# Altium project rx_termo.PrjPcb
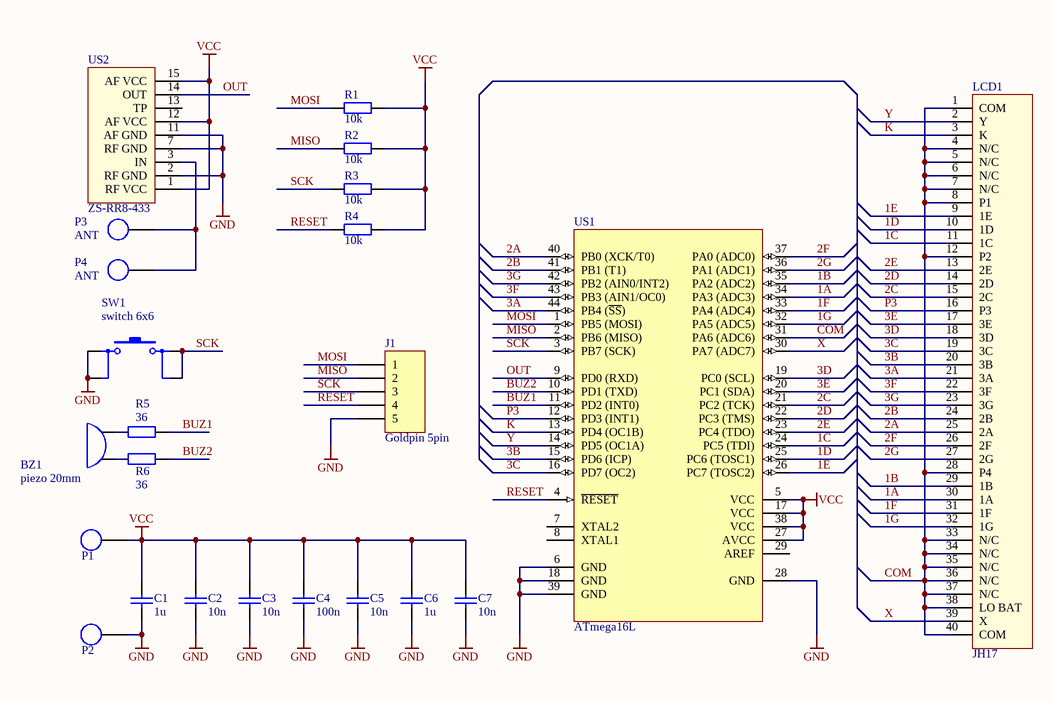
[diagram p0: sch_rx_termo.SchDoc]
1 sheet, 23 parts. Net scope: global (net labels, ports and power ports of the same name join across sheets).
Board file: pcb_rx_termo.PcbDoc

## Sheet sch_rx_termo.SchDoc
size A4

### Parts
BZ1  piezo 20mm  [buzzer piezo - tylko piny]
C1  1u  [MELF-1206]
C2  10n  [MELF-1206]
C3  10n  [MELF-1206]
C4  100n  [MELF-1206]
C5  10n  [MELF-1206]
C6  1u  [MELF-1206]
C7  10n  [MELF-1206]
J1  Goldpin 5pin  [HDR1X5]
LCD1  JH17  [LCD JH17]
P1  Pad  [pad fi 1mm]  (value not drawn)
P2  Pad  [pad fi 1mm]  (value not drawn)
P3  ANT  [Pad SMD 2x4mm]
P4  ANT  [pad fi 1mm]
R1  10k  [MELF-1206]
R2  10k  [MELF-1206]
R3  10k  [MELF-1206]
R4  10k  [MELF-1206]
R5  36  [MELF-1206]
R6  36  [MELF-1206]
SW1  switch 6x6  [tact switch 6x6]
US1  ATmega16L  [44A_N]
US2  ZS-RR8-433  [RR8_Rx]

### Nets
GND: C1.1 C2.1 C3.1 C4.1 C5.1 C6.1 C7.1 J1.5 P2.1 SW1.1 SW1.3 US1.6(GND) US1.18(GND) US1.28(GND) US1.39(GND) US2.2(RF_GND) US2.7(RF_GND) US2.11(AF_GND)
VCC: C1.2 C2.2 C3.2 C4.2 C5.2 C6.2 C7.2 P1.1 R1.1 R2.1 R3.1 R4.1 US1.5(VCC) US1.17(VCC) US1.27(AVCC) US1.38(VCC) US2.1(RF_VCC) US2.12(AF_VCC) US2.15(AF_VCC)
1A: LCD1.30(1A) US1.34(PA3_(ADC3))
1B: LCD1.29(1B) US1.35(PA2_(ADC2))
1C: LCD1.11(1C) US1.24(PC5_(TDI))
1D: LCD1.10(1D) US1.25(PC6_(TOSC1))
1E: LCD1.9(1E) US1.26(PC7_(TOSC2))
1F: LCD1.31(1F) US1.33(PA4_(ADC4))
1G: LCD1.32(1G) US1.32(PA5_(ADC5))
2A: LCD1.25(2A) US1.40(PB0_(XCK/T0))
2B: LCD1.24(2B) US1.41(PB1_(T1))
2C: LCD1.15(2C) US1.21(PC2_(TCK))
2D: LCD1.14(2D) US1.22(PC3_(TMS))
2E: LCD1.13(2E) US1.23(PC4_(TDO))
2F: LCD1.26(2F) US1.37(PA0_(ADC0))
2G: LCD1.27(2G) US1.36(PA1_(ADC1))
3A: LCD1.21(3A) US1.44(PB4_(~{SS}))
3B: LCD1.20(3B) US1.15(PD6_(ICP))
3C: LCD1.19(3C) US1.16(PD7_(OC2))
3D: LCD1.18(3D) US1.19(PC0_(SCL))
3E: LCD1.17(3E) US1.20(PC1_(SDA))
3F: LCD1.22(3F) US1.43(PB3_(AIN1/OC0))
3G: LCD1.23(3G) US1.42(PB2_(AIN0/INT2))
BUZ1: R5.1 US1.11(PD2_(INT0))
BUZ2: R6.1 US1.10(PD1_(TXD))
COM: LCD1.1(COM) LCD1.4(N/C) LCD1.5(N/C) LCD1.6(N/C) LCD1.7(N/C) LCD1.8(P1) LCD1.12(P2) LCD1.28(P4) LCD1.33(N/C) LCD1.34(N/C) LCD1.35(N/C) LCD1.36(N/C) LCD1.37(N/C) LCD1.38(LO_BAT) LCD1.40(COM) US1.31(PA6_(ADC6))
K: LCD1.3(K) US1.13(PD4_(OC1B))
MISO: J1.2 R2.2 US1.2(PB6_(MISO))
MOSI: J1.1 R1.2 US1.1(PB5_(MOSI))
OUT: US1.9(PD0_(RXD)) US2.14(OUT)
P3: LCD1.16(P3) US1.12(PD3_(INT1))
RESET: J1.4 R4.2 US1.4(~{RESET})
SCK: J1.3 R3.2 SW1.2 SW1.4 US1.3(PB7_(SCK))
X: LCD1.39(X) US1.30(PA7_(ADC7))
Y: LCD1.2(Y) US1.14(PD5_(OC1A))
NetBZ1_1: BZ1.1(AF_VCC) R6.2
NetBZ1_2: BZ1.2(AF_VCC) R5.2
NetP3_1: P3.1 P4.1 US2.3(IN)

Not connected (* = marked no-connect by the designer): US1 7(XTAL2) 8(XTAL1) 29(AREF); US2 13(TP)

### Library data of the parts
BZ1 = buzzer piezo
C1-C7 = kondensator
J1 = Header 5: Header, 5-Pin
LCD1 = LCD JH17
P3 P4 = Pad
R1-R6 = rezystor
SW1 = switch
US1 = ATmega32-16AC: 8-Bit AVR Microcontroller with 32K Bytes of In-System Programmable Flash Memory
US2 = RR8_Rx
